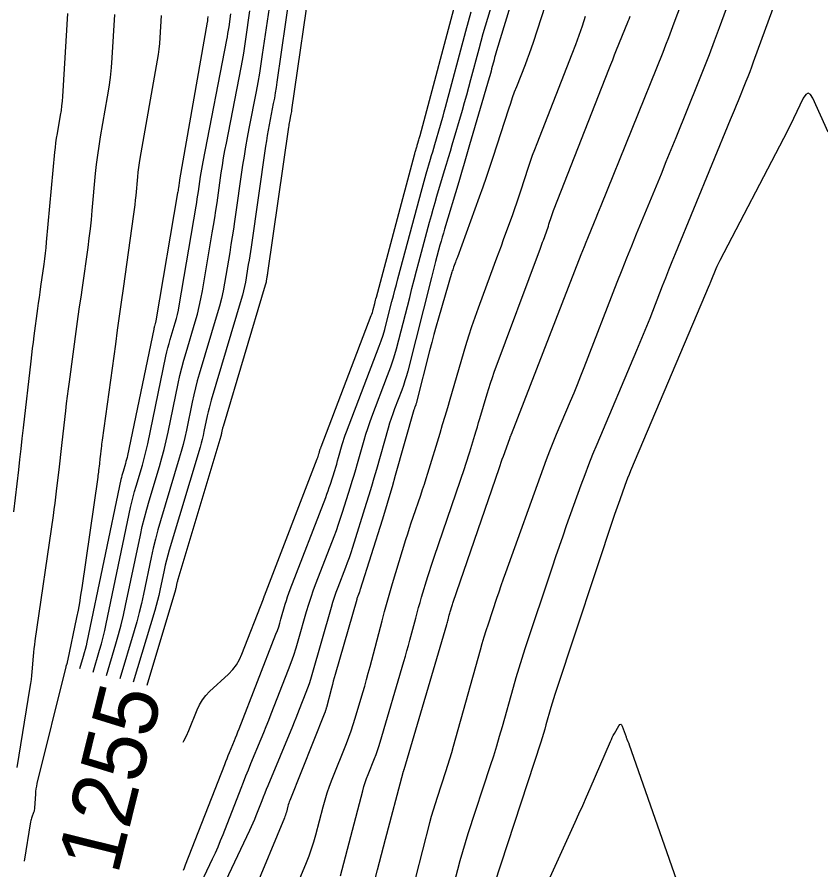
# Model space of a CAD drawing. Extents: x 658976 to 668726, y 639543 to 647196.
# Drawn here: x 661440.5 to 661517.3, y 641084 to 641165.5 of the extents above; entities that cross this region are included whole.
import ezdxf

# ---------------------------------------------------------------- set-up
doc = ezdxf.new("R2010")
doc.units = 0
for name, color, linetype in [('Ex_Contour Labels', 7, 'Continuous'), ('Ex_Major Contours', 7, 'Continuous'), ('Ex_Minor Contours', 7, 'Continuous')]:
    doc.layers.add(name, color=color, linetype=linetype)

msp = doc.modelspace()

# ---------------------------------------------------------------- linework, layer by layer
at = {"layer": 'Ex_Major Contours'}
for points in [[(661466.609, 641167.881), (661465.363, 641159.243), (661465.286, 641158.731), (661465.202, 641158.22), (661465.113, 641157.709), (661465.017, 641157.2), (661464.62, 641155.166), (661464.524, 641154.657), (661464.435, 641154.147), (661464.351, 641153.636), (661464.275, 641153.123), (661462.891, 641143.489), (661462.83, 641143.069), (661462.765, 641142.65), (661462.698, 641142.231), (661462.628, 641141.813), (661462.344, 641140.141), (661462.266, 641139.724), (661462.176, 641139.31), (661462.074, 641138.9), (661461.959, 641138.492), (661459.081, 641128.857), (661458.975, 641128.488), (661458.877, 641128.117), (661458.787, 641127.743), (661458.705, 641127.368), (661458.392, 641125.863), (661458.309, 641125.487), (661458.219, 641125.114), (661458.121, 641124.743), (661458.015, 641124.373), (661455.067, 641114.527), (661454.93, 641114.054), (661454.804, 641113.578), (661454.688, 641113.1), (661454.582, 641112.619), (661454.178, 641110.69), (661454.072, 641110.209), (661453.956, 641109.731), (661453.83, 641109.255), (661453.693, 641108.782), (661451.636, 641101.934)], [(661456.428, 641083.943), (661456.534, 641084.195), (661456.635, 641084.45), (661460.369, 641094.062), (661460.481, 641094.348), (661460.594, 641094.632), (661460.71, 641094.917), (661460.826, 641095.2), (661461.296, 641096.332), (661461.413, 641096.616), (661461.528, 641096.9), (661461.641, 641097.185), (661461.753, 641097.47), (661465.271, 641106.51), (661465.403, 641106.861), (661465.527, 641107.214), (661465.642, 641107.57), (661465.749, 641107.929), (661466.161, 641109.37), (661466.268, 641109.729), (661466.383, 641110.085), (661466.506, 641110.438), (661466.637, 641110.789), (661470.022, 641119.555), (661470.141, 641119.872), (661470.255, 641120.189), (661470.364, 641120.509), (661470.468, 641120.83), (661470.883, 641122.151), (661470.978, 641122.458), (661471.072, 641122.765), (661471.162, 641123.073), (661471.251, 641123.382), (661471.601, 641124.619), (661471.692, 641124.927), (661471.79, 641125.232), (661471.894, 641125.536), (661472.006, 641125.837), (661475.133, 641134.018), (661475.325, 641134.542), (661475.501, 641135.071), (661475.661, 641135.605), (661475.806, 641136.144), (661476.354, 641138.308), (661476.492, 641138.849), (661476.632, 641139.389), (661476.774, 641139.929), (661476.917, 641140.469), (661479.225, 641149.1), (661479.321, 641149.452), (661479.419, 641149.802), (661479.52, 641150.152), (661479.623, 641150.502), (661480.042, 641151.897), (661480.146, 641152.246), (661480.25, 641152.596), (661480.353, 641152.945), (661480.455, 641153.295), (661480.994, 641155.148), (661481.117, 641155.574), (661481.237, 641156), (661481.355, 641156.428), (661481.47, 641156.855), (661483.408, 641164.117), (661483.662, 641165.052), (661483.924, 641165.984)], [(661454.297, 641165.632), (661454.168, 641163.488), (661454.128, 641162.952), (661454.073, 641162.419), (661454.003, 641161.887), (661453.917, 641161.357), (661452.265, 641151.971), (661452.192, 641151.531), (661452.129, 641151.089), (661452.075, 641150.647), (661452.029, 641150.203), (661451.867, 641148.426), (661451.824, 641147.982), (661451.776, 641147.539), (661451.722, 641147.096), (661451.662, 641146.654), (661450.665, 641139.549), (661450.478, 641138.217), (661450.293, 641136.885), (661450.108, 641135.554), (661449.924, 641134.222), (661448.665, 641125.058), (661448.639, 641124.864), (661448.614, 641124.67), (661448.591, 641124.476), (661448.568, 641124.282), (661448.474, 641123.442), (661448.455, 641123.28), (661448.437, 641123.117), (661448.418, 641122.955), (661448.4, 641122.793), (661448.325, 641122.145), (661448.305, 641121.982), (661448.285, 641121.821), (661448.263, 641121.659), (661448.24, 641121.497), (661446.716, 641110.934), (661446.607, 641110.223), (661446.488, 641109.514), (661446.357, 641108.806), (661446.215, 641108.101), (661445.351, 641103.974), (661445.34, 641103.925), (661445.328, 641103.876), (661445.316, 641103.828), (661445.302, 641103.779), (661445.244, 641103.587), (661445.23, 641103.538), (661445.216, 641103.49), (661445.203, 641103.441), (661445.191, 641103.393), (661442.431, 641092.244), (661442.375, 641091.994), (661442.331, 641091.742), (661442.299, 641091.488), (661442.28, 641091.232), (661442.209, 641089.928), (661442.198, 641089.812), (661442.178, 641089.697), (661442.149, 641089.584), (661442.111, 641089.473), (661441.94, 641089.034), (661441.9, 641088.923), (661441.866, 641088.811), (661441.839, 641088.697), (661441.817, 641088.581), (661441.212, 641084.802)], [(661471.438, 641083.428), (661473.57, 641091.551), (661473.68, 641091.946), (661473.802, 641092.336), (661473.935, 641092.722), (661474.081, 641093.105), (661474.688, 641094.627), (661474.835, 641095.009), (661474.973, 641095.394), (661475.102, 641095.783), (661475.222, 641096.174), (661477.492, 641103.886), (661477.641, 641104.399), (661477.786, 641104.914), (661477.928, 641105.429), (661478.066, 641105.945), (661478.62, 641108.051), (661478.753, 641108.548), (661478.891, 641109.045), (661479.034, 641109.54), (661479.181, 641110.034), (661479.778, 641112.006), (661479.929, 641112.499), (661480.085, 641112.99), (661480.246, 641113.48), (661480.41, 641113.968), (661483.282, 641122.352), (661483.415, 641122.746), (661483.545, 641123.14), (661483.671, 641123.536), (661483.794, 641123.933), (661484.278, 641125.522), (661484.399, 641125.92), (661484.518, 641126.318), (661484.637, 641126.716), (661484.754, 641127.115), (661485.442, 641129.462), (661485.6, 641129.985), (661485.767, 641130.505), (661485.944, 641131.021), (661486.129, 641131.535), (661490.539, 641143.402), (661490.609, 641143.593), (661490.68, 641143.784), (661490.75, 641143.975), (661490.82, 641144.166), (661491.104, 641144.947), (661491.169, 641145.131), (661491.234, 641145.314), (661491.296, 641145.499), (661491.357, 641145.684), (661491.597, 641146.426), (661491.659, 641146.61), (661491.723, 641146.794), (661491.79, 641146.977), (661491.86, 641147.159), (661497.072, 641160.457), (661497.257, 641160.926), (661497.442, 641161.395), (661497.63, 641161.863), (661497.818, 641162.331), (661498.896, 641164.999), (661498.924, 641165.068), (661498.951, 641165.137), (661498.977, 641165.207), (661499.003, 641165.277), (661499.104, 641165.556)], [(661489.237, 641078.394), (661493.852, 641088.532), (661494.217, 641089.338), (661494.578, 641090.146), (661494.935, 641090.956), (661495.288, 641091.768), (661497.231, 641096.259), (661497.316, 641096.449), (661497.407, 641096.636), (661497.503, 641096.821), (661497.604, 641097.003), (661498.029, 641097.739), (661498.124, 641097.867), (661498.212, 641097.905), (661498.291, 641097.852), (661498.361, 641097.708), (661498.72, 641096.689), (661498.74, 641096.633), (661498.762, 641096.577), (661498.784, 641096.521), (661498.808, 641096.466), (661498.905, 641096.247), (661498.928, 641096.192), (661498.951, 641096.136), (661498.972, 641096.08), (661498.993, 641096.024), (661504.663, 641079.8)]]:
    msp.add_lwpolyline(points, dxfattribs=at)
at = {"layer": 'Ex_Minor Contours'}
for points in [[(661492.004, 641180.804), (661486.354, 641162.245), (661486.289, 641162.03), (661486.227, 641161.815), (661486.166, 641161.599), (661486.107, 641161.383), (661485.876, 641160.516), (661485.817, 641160.299), (661485.758, 641160.083), (661485.697, 641159.867), (661485.635, 641159.652), (661483.774, 641153.256), (661483.516, 641152.373), (661483.257, 641151.491), (661482.995, 641150.609), (661482.732, 641149.728), (661481.375, 641145.209), (661481.262, 641144.826), (661481.151, 641144.442), (661481.043, 641144.056), (661480.939, 641143.671), (661480.525, 641142.125), (661480.423, 641141.739), (661480.321, 641141.352), (661480.221, 641140.965), (661480.122, 641140.578), (661477.861, 641131.651), (661477.737, 641131.186), (661477.598, 641130.727), (661477.447, 641130.271), (661477.282, 641129.819), (661476.595, 641128.022), (661476.428, 641127.571), (661476.271, 641127.117), (661476.125, 641126.659), (661475.989, 641126.198), (661474.867, 641122.233), (661474.633, 641121.419), (661474.393, 641120.607), (661474.148, 641119.796), (661473.897, 641118.987), (661472.572, 641114.774), (661472.416, 641114.292), (661472.253, 641113.812), (661472.082, 641113.336), (661471.903, 641112.861), (661471.173, 641110.971), (661470.996, 641110.496), (661470.83, 641110.018), (661470.674, 641109.536), (661470.529, 641109.051), (661468.688, 641102.609), (661468.562, 641102.188), (661468.427, 641101.771), (661468.282, 641101.357), (661468.128, 641100.946), (661467.491, 641099.308), (661467.33, 641098.899), (661467.168, 641098.491), (661467.003, 641098.084), (661466.835, 641097.678), (661464.486, 641092.016), (661464.339, 641091.66), (661464.195, 641091.303), (661464.053, 641090.946), (661463.912, 641090.588), (661463.355, 641089.154), (661463.213, 641088.796), (661463.064, 641088.442), (661462.909, 641088.09), (661462.748, 641087.741), (661459.888, 641081.688)], [(661457.878, 641082.21), (661459.218, 641085.049), (661459.482, 641085.62), (661459.736, 641086.197), (661459.98, 641086.777), (661460.213, 641087.362), (661461.928, 641091.777), (661462.161, 641092.373), (661462.398, 641092.967), (661462.638, 641093.559), (661462.881, 641094.151), (661463.861, 641096.513), (661464.105, 641097.104), (661464.345, 641097.697), (661464.582, 641098.291), (661464.815, 641098.886), (661466.469, 641103.136), (661466.724, 641103.814), (661466.963, 641104.497), (661467.186, 641105.185), (661467.393, 641105.879), (661468.189, 641108.665), (661468.396, 641109.359), (661468.618, 641110.047), (661468.856, 641110.731), (661469.109, 641111.409), (661470.824, 641115.85), (661471.041, 641116.425), (661471.248, 641117.003), (661471.446, 641117.584), (661471.635, 641118.168), (661472.39, 641120.569), (661472.563, 641121.127), (661472.732, 641121.686), (661472.898, 641122.246), (661473.059, 641122.808), (661473.695, 641125.056), (661473.861, 641125.616), (661474.038, 641126.172), (661474.228, 641126.724), (661474.431, 641127.271), (661475.937, 641131.212), (661476.245, 641132.055), (661476.529, 641132.906), (661476.787, 641133.764), (661477.02, 641134.63), (661478.045, 641138.678), (661478.26, 641139.524), (661478.479, 641140.37), (661478.701, 641141.215), (661478.925, 641142.06), (661479.948, 641145.883), (661480.116, 641146.503), (661480.289, 641147.121), (661480.466, 641147.738), (661480.648, 641148.353), (661481.387, 641150.813), (661481.571, 641151.428), (661481.753, 641152.043), (661481.935, 641152.659), (661482.114, 641153.275), (661483.077, 641156.585), (661483.287, 641157.313), (661483.493, 641158.043), (661483.694, 641158.774), (661483.892, 641159.506), (661484.674, 641162.437), (661484.873, 641163.169), (661485.078, 641163.899), (661485.289, 641164.627), (661485.507, 641165.353), (661488.713, 641175.884)], [(661494.005, 641175.929), (661489.832, 641163.043), (661489.654, 641162.507), (661489.468, 641161.974), (661489.274, 641161.443), (661489.072, 641160.916), (661488.247, 641158.812), (661488.045, 641158.285), (661487.851, 641157.755), (661487.665, 641157.222), (661487.487, 641156.686), (661485.985, 641152.052), (661485.672, 641151.102), (661485.352, 641150.155), (661485.022, 641149.211), (661484.685, 641148.27), (661482.601, 641142.538), (661482.557, 641142.417), (661482.513, 641142.297), (661482.468, 641142.177), (661482.424, 641142.057), (661482.245, 641141.577), (661482.202, 641141.456), (661482.161, 641141.335), (661482.121, 641141.213), (661482.084, 641141.091), (661480.798, 641136.698), (661480.575, 641135.924), (661480.359, 641135.148), (661480.15, 641134.369), (661479.949, 641133.59), (661478.703, 641128.671), (661478.687, 641128.609), (661478.668, 641128.548), (661478.648, 641128.487), (661478.626, 641128.427), (661478.534, 641128.187), (661478.512, 641128.126), (661478.491, 641128.066), (661478.472, 641128.005), (661478.453, 641127.943), (661476.674, 641121.659), (661476.368, 641120.592), (661476.054, 641119.528), (661475.733, 641118.466), (661475.404, 641117.406), (661473.32, 641110.777), (661473.294, 641110.698), (661473.267, 641110.618), (661473.239, 641110.54), (661473.209, 641110.461), (661473.089, 641110.149), (661473.059, 641110.07), (661473.032, 641109.991), (661473.006, 641109.912), (661472.982, 641109.831), (661470.93, 641102.653), (661470.839, 641102.331), (661470.75, 641102.009), (661470.662, 641101.686), (661470.576, 641101.362), (661470.086, 641099.5), (661470.075, 641099.46), (661470.064, 641099.42), (661470.053, 641099.38), (661470.041, 641099.34), (661469.995, 641099.181), (661469.982, 641099.142), (661469.969, 641099.103), (661469.955, 641099.064), (661469.941, 641099.025), (661466.592, 641090.623), (661466.54, 641090.486), (661466.492, 641090.348), (661466.449, 641090.209), (661466.409, 641090.068), (661466.261, 641089.502), (661466.221, 641089.361), (661466.177, 641089.222), (661466.128, 641089.084), (661466.074, 641088.948), (661463.127, 641081.837)], [(661516.148, 641175.625), (661510.878, 641161.154), (661510.707, 641160.69), (661510.532, 641160.228), (661510.352, 641159.767), (661510.169, 641159.308), (661509.428, 641157.474), (661509.243, 641157.016), (661509.056, 641156.558), (661508.869, 641156.101), (661508.681, 641155.643), (661503.404, 641142.837), (661503.091, 641142.071), (661502.781, 641141.303), (661502.476, 641140.533), (661502.175, 641139.762), (661500.977, 641136.675), (661500.675, 641135.905), (661500.366, 641135.136), (661500.052, 641134.37), (661499.733, 641133.607), (661495.925, 641124.617), (661495.527, 641123.659), (661495.143, 641122.695), (661494.772, 641121.726), (661494.414, 641120.752), (661493.012, 641116.846), (661492.664, 641115.868), (661492.322, 641114.888), (661491.986, 641113.907), (661491.655, 641112.923), (661489.057, 641105.117), (661488.756, 641104.193), (661488.466, 641103.266), (661488.187, 641102.335), (661487.919, 641101.4), (661486.871, 641097.656), (661486.604, 641096.721), (661486.327, 641095.789), (661486.04, 641094.861), (661485.743, 641093.935), (661483.614, 641087.433), (661483.342, 641086.579), (661483.084, 641085.721), (661482.839, 641084.86), (661482.607, 641083.994), (661481.506, 641079.737)], [(661509.928, 641170.788), (661507.622, 641164.456), (661507.144, 641163.161), (661506.655, 641161.871), (661506.154, 641160.584), (661505.643, 641159.302), (661503.47, 641153.927), (661503.004, 641152.776), (661502.535, 641151.625), (661502.065, 641150.475), (661501.592, 641149.326), (661499.699, 641144.731), (661499.229, 641143.581), (661498.765, 641142.429), (661498.306, 641141.274), (661497.854, 641140.117), (661494.684, 641131.946), (661494.37, 641131.144), (661494.049, 641130.344), (661493.722, 641129.547), (661493.389, 641128.753), (661492.045, 641125.579), (661491.715, 641124.784), (661491.396, 641123.984), (661491.088, 641123.18), (661490.791, 641122.371), (661487.198, 641112.361), (661486.981, 641111.75), (661486.767, 641111.139), (661486.557, 641110.526), (661486.351, 641109.912), (661485.532, 641107.452), (661485.331, 641106.836), (661485.138, 641106.218), (661484.952, 641105.597), (661484.774, 641104.975), (661482.202, 641095.783), (661482.027, 641095.17), (661481.845, 641094.558), (661481.656, 641093.948), (661481.461, 641093.341), (661480.667, 641090.914), (661480.473, 641090.306), (661480.289, 641089.696), (661480.114, 641089.082), (661479.95, 641088.465), (661477.924, 641080.64)], [(661468.697, 641170.012), (661466.762, 641156.601), (661466.741, 641156.462), (661466.719, 641156.323), (661466.694, 641156.185), (661466.668, 641156.047), (661466.561, 641155.494), (661466.535, 641155.356), (661466.51, 641155.218), (661466.488, 641155.079), (661466.467, 641154.94), (661464.47, 641141.028), (661464.455, 641140.93), (661464.44, 641140.833), (661464.424, 641140.735), (661464.408, 641140.637), (661464.342, 641140.248), (661464.324, 641140.15), (661464.303, 641140.054), (661464.279, 641139.958), (661464.252, 641139.863), (661460.217, 641126.353), (661460.195, 641126.277), (661460.175, 641126.201), (661460.157, 641126.125), (661460.14, 641126.049), (661460.076, 641125.741), (661460.059, 641125.665), (661460.041, 641125.588), (661460.021, 641125.513), (661459.999, 641125.437), (661455.894, 641111.726), (661455.871, 641111.644), (661455.849, 641111.562), (661455.829, 641111.479), (661455.81, 641111.396), (661455.741, 641111.062), (661455.722, 641110.979), (661455.702, 641110.897), (661455.68, 641110.814), (661455.657, 641110.733), (661452.919, 641101.616)], [(661456.395, 641096.19), (661456.475, 641096.328), (661456.717, 641096.804), (661456.933, 641097.295), (661457.741, 641099.287), (661457.967, 641099.769), (661458.241, 641100.218), (661458.562, 641100.634), (661458.931, 641101.017), (661460.73, 641102.699), (661461.133, 641103.12), (661461.482, 641103.578), (661461.778, 641104.072), (661462.018, 641104.603), (661464.073, 641109.884), (661464.082, 641109.907), (661464.09, 641109.931), (661464.098, 641109.955), (661464.105, 641109.979), (661464.133, 641110.075), (661464.14, 641110.099), (661464.148, 641110.122), (661464.156, 641110.146), (661464.165, 641110.169), (661469.22, 641123.261), (661469.241, 641123.318), (661469.262, 641123.376), (661469.282, 641123.434), (661469.301, 641123.492), (661469.376, 641123.732), (661469.394, 641123.788), (661469.411, 641123.844), (661469.427, 641123.9), (661469.443, 641123.956), (661469.507, 641124.181), (661469.523, 641124.237), (661469.541, 641124.293), (661469.56, 641124.348), (661469.58, 641124.403), (661474.377, 641136.95), (661474.429, 641137.092), (661474.477, 641137.236), (661474.521, 641137.381), (661474.56, 641137.527), (661474.709, 641138.115), (661474.746, 641138.262), (661474.784, 641138.409), (661474.823, 641138.555), (661474.862, 641138.702), (661478.503, 641152.317), (661478.526, 641152.4), (661478.549, 641152.484), (661478.573, 641152.567), (661478.597, 641152.65), (661478.697, 641152.982), (661478.722, 641153.065), (661478.746, 641153.148), (661478.771, 641153.231), (661478.795, 641153.314), (661478.923, 641153.755), (661478.953, 641153.856), (661478.981, 641153.958), (661479.009, 641154.059), (661479.037, 641154.161), (661482.65, 641167.699)], [(661474.223, 641081.08), (661474.978, 641083.998), (661475.167, 641084.727), (661475.357, 641085.456), (661475.547, 641086.185), (661475.738, 641086.914), (661477.412, 641093.29), (661477.418, 641093.315), (661477.426, 641093.34), (661477.435, 641093.364), (661477.444, 641093.388), (661477.482, 641093.484), (661477.491, 641093.508), (661477.5, 641093.532), (661477.508, 641093.556), (661477.515, 641093.581), (661481.595, 641107.442), (661481.626, 641107.55), (661481.656, 641107.658), (661481.686, 641107.766), (661481.715, 641107.875), (661481.832, 641108.317), (661481.86, 641108.422), (661481.889, 641108.526), (661481.919, 641108.63), (661481.95, 641108.734), (661482.075, 641109.148), (661482.107, 641109.252), (661482.14, 641109.355), (661482.173, 641109.458), (661482.208, 641109.56), (661486.585, 641122.34), (661486.687, 641122.635), (661486.79, 641122.93), (661486.893, 641123.224), (661486.998, 641123.518), (661487.606, 641125.211), (661487.619, 641125.245), (661487.632, 641125.279), (661487.645, 641125.313), (661487.659, 641125.346), (661487.716, 641125.48), (661487.73, 641125.513), (661487.743, 641125.547), (661487.757, 641125.581), (661487.77, 641125.615), (661494.426, 641142.773), (661494.58, 641143.167), (661494.736, 641143.56), (661494.894, 641143.952), (661495.054, 641144.343), (661495.698, 641145.907), (661495.859, 641146.298), (661496.019, 641146.69), (661496.179, 641147.081), (661496.337, 641147.473), (661502.252, 641162.109), (661502.53, 641162.805), (661502.802, 641163.504), (661503.068, 641164.205), (661503.328, 641164.909), (661504.354, 641167.728)], [(661449.072, 641102.569), (661449.973, 641105.569), (661450.236, 641106.48), (661450.479, 641107.396), (661450.703, 641108.316), (661450.907, 641109.242), (661452.313, 641115.956), (661452.496, 641116.788), (661452.697, 641117.615), (661452.915, 641118.438), (661453.151, 641119.257), (661454.128, 641122.522), (661454.364, 641123.341), (661454.581, 641124.164), (661454.781, 641124.991), (661454.964, 641125.823), (661455.928, 641130.463), (661456.092, 641131.209), (661456.271, 641131.95), (661456.465, 641132.687), (661456.676, 641133.42), (661457.55, 641136.346), (661457.757, 641137.08), (661457.941, 641137.819), (661458.103, 641138.563), (661458.243, 641139.313), (661459.187, 641144.856), (661459.306, 641145.57), (661459.42, 641146.284), (661459.53, 641146.999), (661459.635, 641147.715), (661460.046, 641150.579), (661460.153, 641151.294), (661460.27, 641152.008), (661460.395, 641152.72), (661460.529, 641153.431), (661461.938, 641160.664), (661462.065, 641161.336), (661462.184, 641162.009), (661462.294, 641162.684), (661462.395, 641163.361), (661462.786, 641166.069)], [(661464.609, 641166.365), (661463.963, 641161.885), (661463.83, 641160.999), (661463.686, 641160.116), (661463.531, 641159.234), (661463.365, 641158.354), (661462.679, 641154.838), (661462.514, 641153.958), (661462.359, 641153.076), (661462.215, 641152.193), (661462.082, 641151.307), (661461.313, 641145.949), (661461.204, 641145.208), (661461.09, 641144.467), (661460.972, 641143.728), (661460.848, 641142.989), (661460.345, 641140.034), (661460.209, 641139.298), (661460.05, 641138.567), (661459.868, 641137.841), (661459.665, 641137.121), (661457.945, 641131.362), (661457.755, 641130.699), (661457.579, 641130.032), (661457.417, 641129.362), (661457.269, 641128.688), (661456.707, 641125.984), (661456.559, 641125.31), (661456.397, 641124.64), (661456.221, 641123.973), (661456.03, 641123.31), (661454.239, 641117.328), (661453.99, 641116.464), (661453.76, 641115.594), (661453.548, 641114.72), (661453.354, 641113.842), (661452.616, 641110.318), (661452.422, 641109.439), (661452.21, 641108.565), (661451.979, 641107.696), (661451.729, 641106.831), (661450.354, 641102.251)], [(661440.224, 641118.199), (661440.689, 641122.208), (661440.804, 641123.21), (661440.919, 641124.212), (661441.033, 641125.215), (661441.146, 641126.217), (661441.863, 641132.595), (661441.933, 641133.204), (661442.007, 641133.812), (661442.085, 641134.42), (661442.166, 641135.027), (661442.521, 641137.61), (661442.594, 641138.14), (661442.667, 641138.669), (661442.741, 641139.199), (661442.815, 641139.728), (661443.113, 641141.845), (661443.184, 641142.375), (661443.248, 641142.905), (661443.307, 641143.436), (661443.358, 641143.968), (661444.142, 641152.57), (661444.188, 641153.015), (661444.242, 641153.459), (661444.306, 641153.902), (661444.379, 641154.344), (661444.689, 641156.108), (661444.761, 641156.55), (661444.819, 641156.993), (661444.865, 641157.438), (661444.899, 641157.884), (661445.378, 641165.827)], [(661449.838, 641165.73), (661449.588, 641161.584), (661449.517, 641160.645), (661449.421, 641159.709), (661449.297, 641158.776), (661449.147, 641157.846), (661448.474, 641154.021), (661448.33, 641153.148), (661448.204, 641152.272), (661448.096, 641151.393), (661448.006, 641150.513), (661447.685, 641146.985), (661447.599, 641146.103), (661447.503, 641145.223), (661447.395, 641144.344), (661447.278, 641143.466), (661446.74, 641139.638), (661446.61, 641138.708), (661446.48, 641137.777), (661446.351, 641136.847), (661446.223, 641135.916), (661445.497, 641130.632), (661445.403, 641129.937), (661445.314, 641129.241), (661445.229, 641128.544), (661445.149, 641127.848), (661444.81, 641124.83), (661444.744, 641124.247), (661444.678, 641123.665), (661444.611, 641123.083), (661444.544, 641122.5), (661444.274, 641120.172), (661444.205, 641119.59), (661444.131, 641119.009), (661444.054, 641118.428), (661443.972, 641117.847), (661442.243, 641105.87), (661442.193, 641105.502), (661442.148, 641105.133), (661442.108, 641104.764), (661442.074, 641104.394), (661441.949, 641102.912), (661441.914, 641102.542), (661441.871, 641102.173), (661441.822, 641101.805), (661441.765, 641101.438), (661440.496, 641093.762)], [(661458.757, 641165.535), (661458.741, 641165.263), (661458.736, 641165.196), (661458.729, 641165.128), (661458.72, 641165.061), (661458.709, 641164.994), (661456.056, 641149.92), (661456.054, 641149.907), (661456.053, 641149.894), (661456.05, 641149.867), (661456.049, 641149.854), (661456.047, 641149.841), (661455.949, 641149.142), (661455.932, 641149.023), (661455.914, 641148.904), (661455.895, 641148.786), (661455.875, 641148.668), (661453.794, 641136.445), (661453.782, 641136.379), (661453.768, 641136.313), (661453.752, 641136.248), (661453.733, 641136.183), (661453.656, 641135.924), (661453.637, 641135.859), (661453.62, 641135.794), (661453.604, 641135.729), (661453.59, 641135.663), (661451.08, 641123.591), (661451.037, 641123.396), (661450.99, 641123.201), (661450.939, 641123.008), (661450.884, 641122.816), (661450.654, 641122.049), (661450.599, 641121.857), (661450.548, 641121.663), (661450.501, 641121.469), (661450.458, 641121.274), (661447.203, 641105.73), (661447.128, 641105.389), (661447.045, 641105.049), (661446.956, 641104.712), (661446.859, 641104.376), (661446.507, 641103.204)], [(661447.789, 641102.887), (661448.416, 641104.973), (661448.596, 641105.596), (661448.762, 641106.222), (661448.915, 641106.852), (661449.055, 641107.486), (661451.385, 641118.615), (661451.498, 641119.128), (661451.622, 641119.639), (661451.757, 641120.147), (661451.902, 641120.653), (661452.506, 641122.669), (661452.651, 641123.174), (661452.786, 641123.683), (661452.909, 641124.193), (661453.022, 641124.707), (661454.759, 641133.063), (661454.848, 641133.469), (661454.945, 641133.872), (661455.051, 641134.273), (661455.166, 641134.672), (661455.641, 641136.264), (661455.754, 641136.664), (661455.855, 641137.066), (661455.943, 641137.471), (661456.019, 641137.879), (661457.638, 641147.392), (661457.697, 641147.746), (661457.754, 641148.1), (661457.808, 641148.455), (661457.861, 641148.81), (661458.065, 641150.231), (661458.118, 641150.586), (661458.176, 641150.941), (661458.238, 641151.294), (661458.304, 641151.647), (661460.572, 641163.282), (661460.631, 641163.592), (661460.685, 641163.902), (661460.736, 641164.214), (661460.783, 641164.525), (661460.963, 641165.774)], [(661466.951, 641081.705), (661468.188, 641084.69), (661468.443, 641085.336), (661468.676, 641085.988), (661468.885, 641086.649), (661469.073, 641087.317), (661469.778, 641090.004), (661469.965, 641090.672), (661470.171, 641091.334), (661470.398, 641091.989), (661470.645, 641092.638), (661472.006, 641096.054), (661472.237, 641096.652), (661472.453, 641097.255), (661472.655, 641097.863), (661472.843, 641098.475), (661473.567, 641100.935), (661473.746, 641101.551), (661473.92, 641102.168), (661474.09, 641102.786), (661474.256, 641103.406), (661475.408, 641107.784), (661475.647, 641108.675), (661475.894, 641109.564), (661476.149, 641110.45), (661476.412, 641111.334), (661477.693, 641115.566), (661477.857, 641116.097), (661478.025, 641116.627), (661478.198, 641117.155), (661478.376, 641117.682), (661479.097, 641119.787), (661479.275, 641120.314), (661479.448, 641120.842), (661479.617, 641121.372), (661479.781, 641121.903), (661480.944, 641125.718), (661481.191, 641126.531), (661481.435, 641127.345), (661481.677, 641128.16), (661481.917, 641128.975), (661483.419, 641134.102), (661483.694, 641135.01), (661483.984, 641135.913), (661484.291, 641136.811), (661484.614, 641137.703), (661486.162, 641141.87), (661486.379, 641142.455), (661486.595, 641143.041), (661486.809, 641143.627), (661487.023, 641144.213), (661487.894, 641146.608), (661488.096, 641147.171), (661488.293, 641147.735), (661488.484, 641148.301), (661488.671, 641148.868), (661489.408, 641151.142), (661489.596, 641151.708), (661489.793, 641152.272), (661489.998, 641152.833), (661490.212, 641153.391), (661493.577, 641161.974), (661493.916, 641162.859), (661494.242, 641163.749), (661494.554, 641164.644), (661494.853, 641165.544)], [(661518.038, 641154.462), (661516.559, 641157.713), (661516.336, 641158.08), (661516.11, 641158.204), (661515.883, 641158.084), (661515.653, 641157.722), (661514.729, 641155.785), (661514.496, 641155.302), (661514.258, 641154.821), (661514.016, 641154.342), (661513.77, 641153.866), (661507.682, 641142.226), (661507.581, 641142.027), (661507.484, 641141.826), (661507.392, 641141.623), (661507.305, 641141.418), (661506.82, 641140.242), (661506.807, 641140.21), (661506.794, 641140.178), (661506.782, 641140.147), (661506.769, 641140.115), (661506.72, 641139.988), (661506.708, 641139.956), (661506.695, 641139.924), (661506.682, 641139.893), (661506.669, 641139.861), (661499.145, 641122.098), (661499.004, 641121.758), (661498.868, 641121.415), (661498.736, 641121.071), (661498.609, 641120.725), (661498.111, 641119.337), (661497.987, 641118.99), (661497.866, 641118.642), (661497.746, 641118.293), (661497.629, 641117.944), (661492.035, 641101.138), (661491.902, 641100.729), (661491.773, 641100.319), (661491.65, 641099.908), (661491.532, 641099.495), (661491.069, 641097.84), (661490.951, 641097.427), (661490.828, 641097.015), (661490.701, 641096.605), (661490.57, 641096.196), (661486.116, 641082.588)]]:
    msp.add_lwpolyline(points, dxfattribs=at)

# ---------------------------------------------------------------- texts
at = {"layer": 'Ex_Contour Labels'}
msp.add_text('1255', height=6, rotation=76.09044, dxfattribs=at).set_placement((661450.141, 641083.417))

doc.saveas('drawing.dxf')
